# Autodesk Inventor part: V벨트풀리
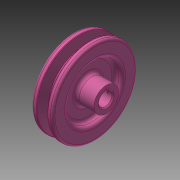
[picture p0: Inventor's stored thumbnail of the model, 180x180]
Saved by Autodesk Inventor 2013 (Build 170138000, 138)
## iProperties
Created: 2015-11
Part Number: V벨트풀리
Material: 강철, 탄소
Document SubType Name: Modeling
Designer: mduedu
Density: 1 g/cm^3
Author: mduedu
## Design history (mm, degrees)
sketch "스케치1"
  geometry: L1 (-9.5, 0)-(9.5, 0); L2 (0, 0)-(0, 37.7); L3 (-4.825, 37.7)-(-9.5, 37.7); L4 (-9.5, 37.7)-(-9.5, 0); L5 (0, 28.7)-(-2.074, 28.7); L6 (-2.074, 28.7)-(-4.825, 37.7); L7 (4.825, 37.7)-(9.5, 37.7); L8 (9.5, 37.7)-(9.5, 0); L9 (0, 28.7)-(2.074, 28.7); L10 (2.074, 28.7)-(4.825, 37.7); L11 (-9.5, 35)-(9.5, 35); 3 further points
  constraints: 22 end point, 7 point on line, 4 perpendicular, 3 symmetric about line, 1 coincident, 1 horizontal, 1 horizontal alignment, 1 midpoint, 1 vertical
  dimensions: "d0" = 19 distance of L1.start L1.end; "d2" = 75.4 diameter of L2.end L1 (derived); "d3" = 34 deg angle of L10 L6; "d4" = 6.3 distance between parallel lines of L11 L9; "d5" = 2.7 distance between parallel lines of L7 L11; "d6" = 8 distance of point (4, 35) point (-4, 35); "d7" = 70 diameter of L11 L1
revolve "회전1" sketch "스케치1" stored, may be unused: angle "d8" = 90 deg
sketch "스케치2"
  geometry: C1 r 24 at (0, 0); C2 r 11 at (0, 0); 1 further point
  constraints: 2 centre point, 2 coincident
  dimensions: "d9" = 48 diameter of C1; "d10" = 22 diameter of C2
extrude "돌출1" cut sketch "스케치2" distance "d11" = 6; taper "d12" = 0 deg
extrude "돌출3" join sketch "스케치2" distance "d37" = 10; taper "d38" = 0 deg
fillet "모깎기1" dims "d13" = 3
fillet "모깎기2" dims "d14" = 3
fillet "모깎기3" dims "d15" = 1, "d16" = 0.5, "d17" = 2
hole "구멍1" diameter "d20" = 12; stored, may be unused: countersink angle "d24" = 90 deg, drill point angle "d26" = 118 deg; dims "d21" = 6, "d22" = 4, "d23" = 2, "d25" = 8, "d39" = 10, "d40" = 10
sketch "스케치3"
  geometry: L1 (-2, 0)-(2, 0); L2 (2, 0)-(2, 7.8); L3 (2, 7.8)-(-2, 7.8); L4 (-2, 7.8)-(-2, 0); 2 further points
  constraints: 8 end point, 2 parallel, 1 coincident, 1 horizontal, 1 midpoint, 1 perpendicular
  dimensions: "d27" = 4 distance of L2.end L3.end; "d29" = 7.8 distance of L3.end L1.start
extrude "돌출2" cut sketch "스케치3" stored distance "d30" = 6; taper "d31" = 0 deg
chamfer "모따기1" distance "d32" = 1; stored, may be unused: second distance "d33" = 2, angle "d34" = 45 deg
node "작업 평면1"
sketch "스케치4"
  geometry: L1 (-19, 11)-(-19, -11) reference; 2 further points
  constraints: 1 horizontal alignment
  dimensions: "d41" = 25 distance from line of point (6, 0) L1
hole "구멍2" sketch "스케치4" at (6, 0) diameter "d42" = 2.459; stored, may be unused: countersink angle "d46" = 90 deg, drill point angle "d48" = 118 deg; dims "d43" = 6, "d44" = 4, "d45" = 2, "d47" = 8
chamfer "모따기2" distance "d49" = 1; stored, may be unused: second distance "d50" = 2, angle "d51" = 45 deg
node "솔리드1"
mirror "대칭1"
